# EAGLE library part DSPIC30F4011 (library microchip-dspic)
dsPIC Motion Controller DSP
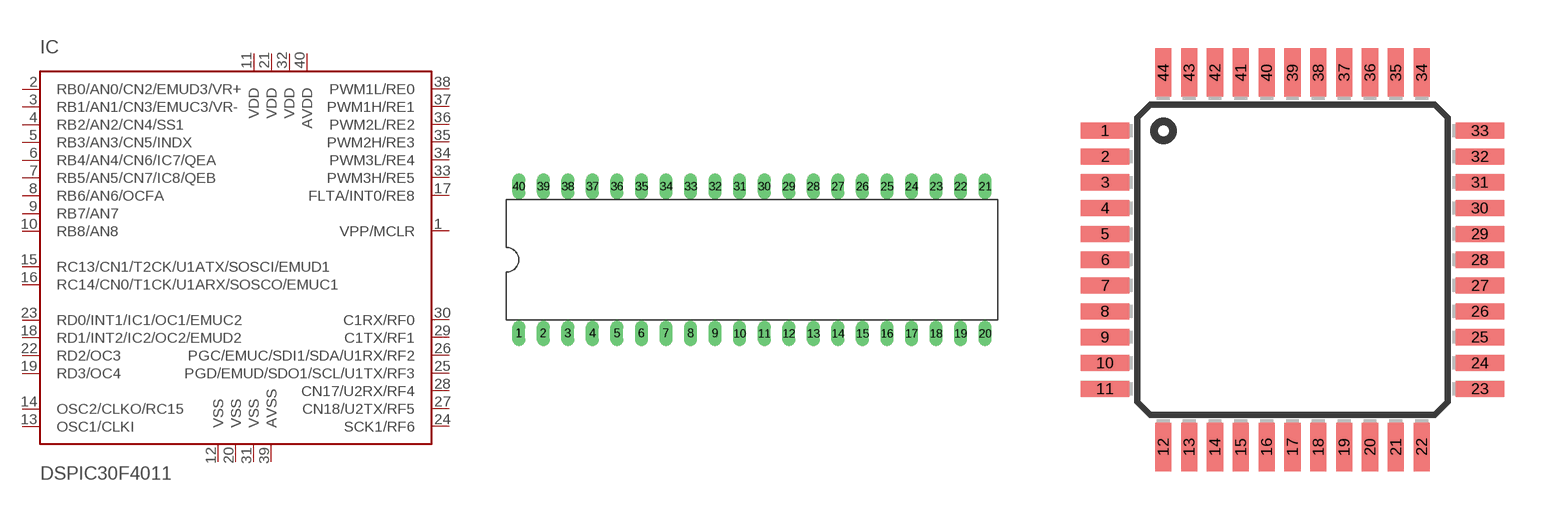
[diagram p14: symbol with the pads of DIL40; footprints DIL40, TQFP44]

Designator prefix IC

## DSPIC30F4011/P  [DIL40]
1  VPP/MCLR  in
2  RB0/AN0/CN2/EMUD3/VR+
3  RB1/AN1/CN3/EMUC3/VR-
4  RB2/AN2/CN4/SS1
5  RB3/AN3/CN5/INDX
6  RB4/AN4/CN6/IC7/QEA
7  RB5/AN5/CN7/IC8/QEB
8  RB6/AN6/OCFA
9  RB7/AN7
10  RB8/AN8
11  VDD  pwr
12  VSS  pwr
13  OSC1/CLKI  in
14  OSC2/CLKO/RC15
15  RC13/CN1/T2CK/U1ATX/SOSCI/EMUD1
16  RC14/CN0/T1CK/U1ARX/SOSCO/EMUC1
17  FLTA/INT0/RE8
18  RD1/INT2/IC2/OC2/EMUD2
19  RD3/OC4
20  VSS  pwr
21  VDD  pwr
22  RD2/OC3
23  RD0/INT1/IC1/OC1/EMUC2
24  SCK1/RF6
25  PGD/EMUD/SDO1/SCL/U1TX/RF3
26  PGC/EMUC/SDI1/SDA/U1RX/RF2
27  CN18/U2TX/RF5
28  CN17/U2RX/RF4
29  C1TX/RF1
30  C1RX/RF0
31  VSS  pwr
32  VDD  pwr
33  PWM3H/RE5
34  PWM3L/RE4
35  PWM2H/RE3
36  PWM2L/RE2
37  PWM1H/RE1
38  PWM1L/RE0
39  AVSS  pwr
40  AVDD  pwr

## DSPIC30F4011/PT  [TQFP44]
1  PGC/EMUC/SDI1/SDA/U1RX/RF2
2  CN18/U2TX/RF5
3  CN17/U2RX/RF4
4  C1TX/RF1
5  C1RX/RF0
6  VSS  pwr
7  VDD  pwr
8  PWM3H/RE5
9  PWM3L/RE4
10  PWM2H/RE3
11  PWM2L/RE2
14  PWM1H/RE1
15  PWM1L/RE0
16  AVSS  pwr
17  AVDD  pwr
18  VPP/MCLR  in
19  RB0/AN0/CN2/EMUD3/VR+
20  RB1/AN1/CN3/EMUC3/VR-
21  RB2/AN2/CN4/SS1
22  RB3/AN3/CN5/INDX
23  RB4/AN4/CN6/IC7/QEA
24  RB5/AN5/CN7/IC8/QEB
25  RB6/AN6/OCFA
26  RB7/AN7
27  RB8/AN8
28  VDD  pwr
29  VSS  pwr
30  OSC1/CLKI  in
31  OSC2/CLKO/RC15
32  RC13/CN1/T2CK/U1ATX/SOSCI/EMUD1
35  RC14/CN0/T1CK/U1ARX/SOSCO/EMUC1
36  FLTA/INT0/RE8
37  RD1/INT2/IC2/OC2/EMUD2
38  RD3/OC4
39  VSS  pwr
40  VDD  pwr
41  RD2/OC3
42  RD0/INT1/IC1/OC1/EMUC2
43  SCK1/RF6
44  PGD/EMUD/SDO1/SCL/U1TX/RF3

## DSPIC30F4011/ML  [QFN44-8X8]
1  PGC/EMUC/SDI1/SDA/U1RX/RF2
2  CN18/U2TX/RF5
3  CN17/U2RX/RF4
4  C1TX/RF1
5  C1RX/RF0
6  VSS  pwr
7  VDD  pwr
9  PWM3H/RE5
10  PWM3L/RE4
11  PWM2H/RE3
12  PWM2L/RE2
14  PWM1H/RE1
15  PWM1L/RE0
16  AVSS  pwr
17  AVDD  pwr
18  VPP/MCLR  in
19  RB0/AN0/CN2/EMUD3/VR+
20  RB1/AN1/CN3/EMUC3/VR-
21  RB2/AN2/CN4/SS1
22  RB3/AN3/CN5/INDX
23  RB4/AN4/CN6/IC7/QEA
24  RB5/AN5/CN7/IC8/QEB
25  RB6/AN6/OCFA
26  RB7/AN7
27  RB8/AN8
28  VDD  pwr
30  VSS  pwr
32  OSC1/CLKI  in
33  OSC2/CLKO/RC15
34  RC13/CN1/T2CK/U1ATX/SOSCI/EMUD1
35  RC14/CN0/T1CK/U1ARX/SOSCO/EMUC1
36  FLTA/INT0/RE8
37  RD1/INT2/IC2/OC2/EMUD2
38  RD3/OC4
39  VSS  pwr
40  VDD  pwr
41  RD2/OC3
42  RD0/INT1/IC1/OC1/EMUC2
43  SCK1/RF6
44  PGD/EMUD/SDO1/SCL/U1TX/RF3

## Footprint DIL40 (pad centres in mm)
Dual In Line package type P
drill 0.813 long: 1 -24.13,-7.62; 2 -21.59,-7.62; 3 -19.05,-7.62; 4 -16.51,-7.62; 5 -13.97,-7.62; 6 -11.43,-7.62; 7 -8.89,-7.62; 8 -6.35,-7.62; 9 -3.81,-7.62; 10 -1.27,-7.62; 11 1.27,-7.62; 12 3.81,-7.62; 13 6.35,-7.62; 14 8.89,-7.62; 15 11.43,-7.62; 16 13.97,-7.62; 17 16.51,-7.62; 18 19.05,-7.62; 19 21.59,-7.62; 20 24.13,-7.62; 21 24.13,7.62; 22 21.59,7.62; 23 19.05,7.62; 24 16.51,7.62; 25 13.97,7.62; 26 11.43,7.62; 27 8.89,7.62; 28 6.35,7.62; 29 3.81,7.62; 30 1.27,7.62; 31 -1.27,7.62; 32 -3.81,7.62; 33 -6.35,7.62; 34 -8.89,7.62; 35 -11.43,7.62; 36 -13.97,7.62; 37 -16.51,7.62; 38 -19.05,7.62; 39 -21.59,7.62; 40 -24.13,7.62

## Footprint TQFP44 (pad centres in mm)
Thin Quad Flat Pack package type TQ
smd 1.5 x 0.5: 1 -5.8,4; 2 -5.8,3.2; 3 -5.8,2.4; 4 -5.8,1.6; 5 -5.8,0.8; 6 -5.8,0; 7 -5.8,-0.8; 8 -5.8,-1.6; 9 -5.8,-2.4; 10 -5.8,-3.2; 11 -5.8,-4; 23 5.8,-4; 24 5.8,-3.2; 25 5.8,-2.4; 26 5.8,-1.6; 27 5.8,-0.8; 28 5.8,0; 29 5.8,0.8; 30 5.8,1.6; 31 5.8,2.4; 32 5.8,3.2; 33 5.8,4
smd 0.5 x 1.5: 12 -4,-5.8; 13 -3.2,-5.8; 14 -2.4,-5.8; 15 -1.6,-5.8; 16 -0.8,-5.8; 17 0,-5.8; 18 0.8,-5.8; 19 1.6,-5.8; 20 2.4,-5.8; 21 3.2,-5.8; 22 4,-5.8; 34 4,5.8; 35 3.2,5.8; 36 2.4,5.8; 37 1.6,5.8; 38 0.8,5.8; 39 0,5.8; 40 -0.8,5.8; 41 -1.6,5.8; 42 -2.4,5.8; 43 -3.2,5.8; 44 -4,5.8

## Footprint QFN44-8X8 (pad centres in mm)
Quad Flat No Lead
smd 0.6 x 0.37: 1 3.825,-3.25; 2 3.825,-2.6; 3 3.825,-1.95; 4 3.825,-1.3; 5 3.825,-0.65; 6 3.825,0; 7 3.825,0.65; 8 3.825,1.3; 9 3.825,1.95; 10 3.825,2.6; 11 3.825,3.25; 23 -3.825,3.25; 24 -3.825,2.6; 25 -3.825,1.95; 26 -3.825,1.3; 27 -3.825,0.65; 28 -3.825,0; 29 -3.825,-0.65; 30 -3.825,-1.3; 31 -3.825,-1.95; 32 -3.825,-2.6; 33 -3.825,-3.25
smd 0.37 x 0.6: 12 3.25,3.825; 13 2.6,3.825; 14 1.95,3.825; 15 1.3,3.825; 16 0.65,3.825; 17 0,3.825; 18 -0.65,3.825; 19 -1.3,3.825; 20 -1.95,3.825; 21 -2.6,3.825; 22 -3.25,3.825; 34 -3.25,-3.825; 35 -2.6,-3.825; 36 -1.95,-3.825; 37 -1.3,-3.825; 38 -0.65,-3.825; 39 0,-3.825; 40 0.65,-3.825; 41 1.3,-3.825; 42 1.95,-3.825; 43 2.6,-3.825; 44 3.25,-3.825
